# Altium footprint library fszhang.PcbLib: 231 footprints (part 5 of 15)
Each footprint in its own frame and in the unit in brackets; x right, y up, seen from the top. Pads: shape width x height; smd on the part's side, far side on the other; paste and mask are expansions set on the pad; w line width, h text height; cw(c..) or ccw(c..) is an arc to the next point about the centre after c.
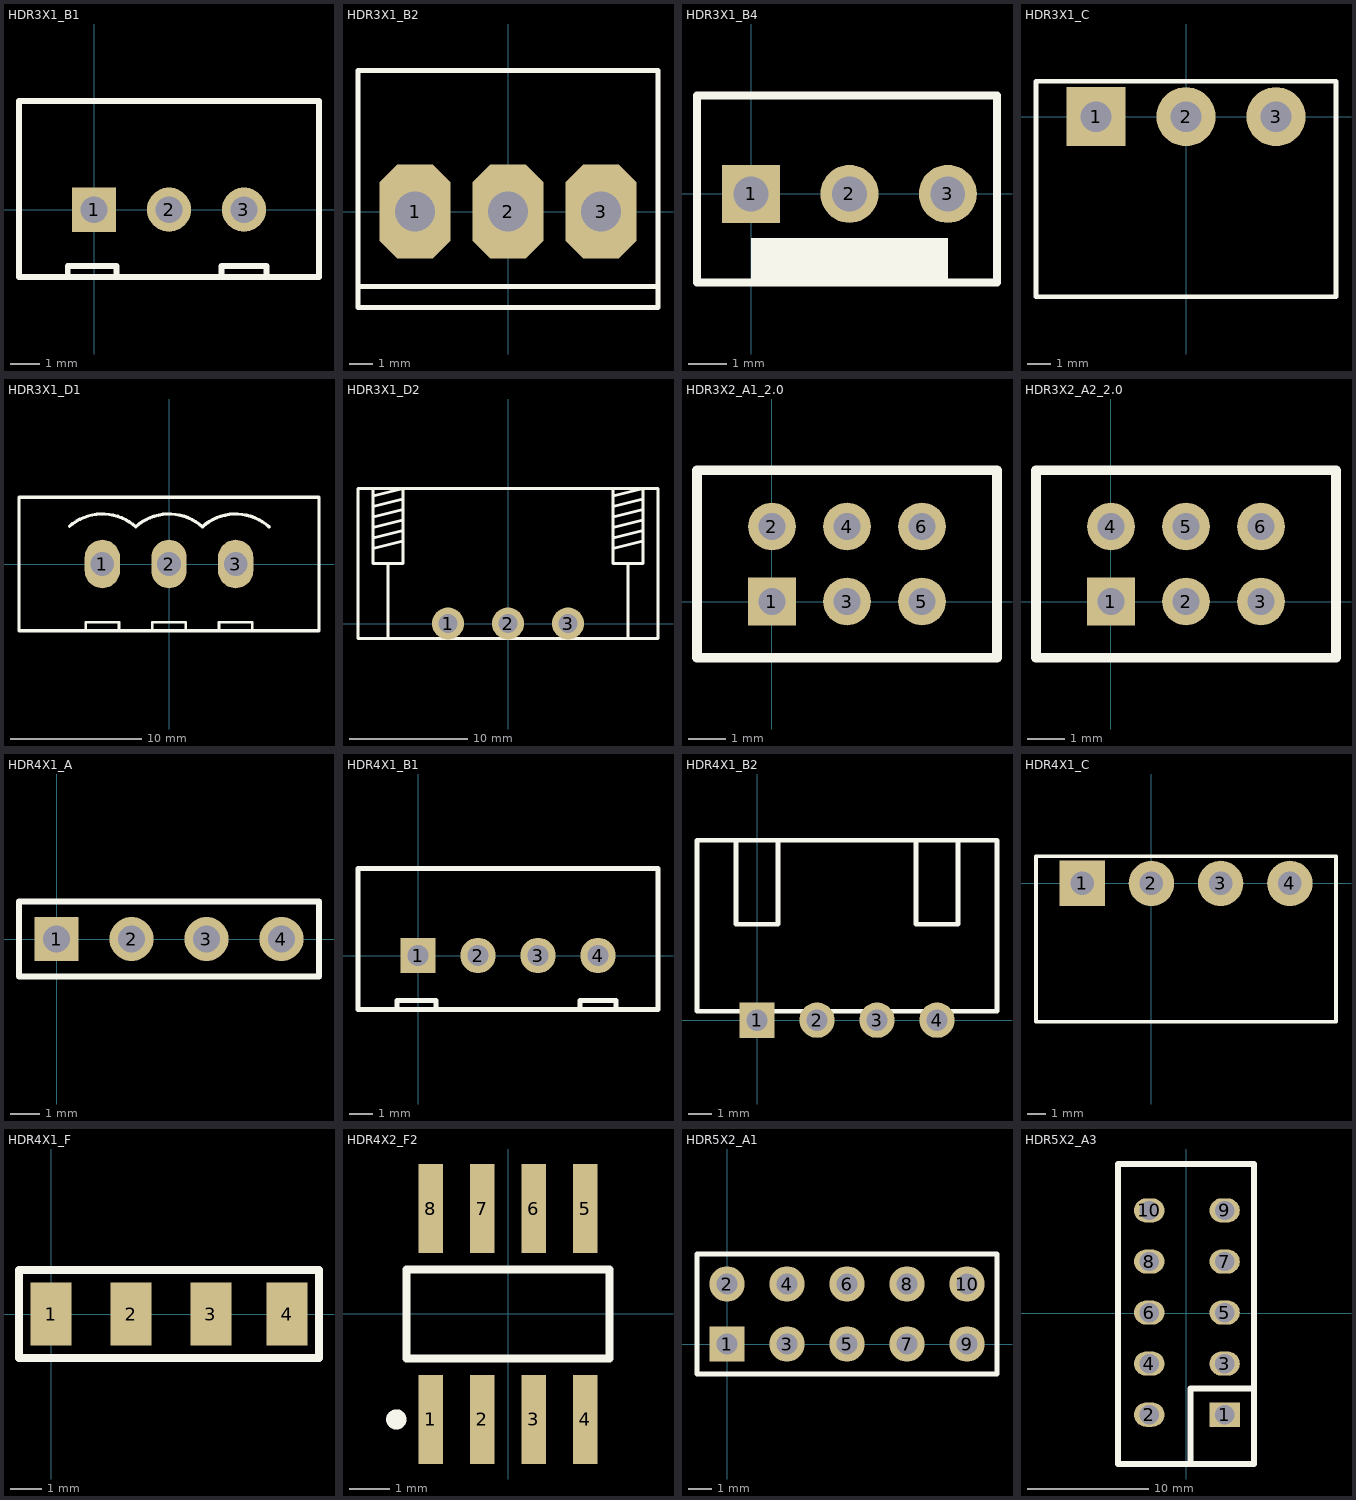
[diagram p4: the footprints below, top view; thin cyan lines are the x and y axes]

## HDR3X1_B1 [mm] "Connector; Header; 3 Position"
height 1.5
pads (3):
  rect 1.5x1.5 hole 0.9: 1(0,0)
  round 1.5 hole 0.9: 2(2.54,0) 3(5.08,0)
Top Overlay:
  lines w0.2: -0.889,-2.286 -0.889,-1.905 0.762,-1.905 0.762,-2.286 ; 4.318,-2.286 4.318,-1.905 5.842,-1.905 5.842,-2.286 ; -2.54,-2.286 -2.54,3.683 7.62,3.683 7.62,-2.286 -2.54,-2.286
3D body: height 1.5, standoff 0, extent -2.54,-2.286 7.62,3.683

## HDR3X1_B2 [mm] "Connector; Header; 3 Position"
height 1.5
pads (3):
  oct 3x4 hole 1.7: 1(-3.937,0) 2(0,0) 3(3.937,0)
Top Overlay:
  lines w0.2: -6.35,-3.175 6.35,-3.175 ; -2.54,-4.064 2.54,-4.064 ; -6.35,-4.064 -6.35,5.969 6.35,5.969 6.35,-4.064 -6.35,-4.064

## HDR3X1_B4 [mm] "Connector; Header; 4 Position"
height 1.6
pads (3):
  rect 1.5x1.5 hole 0.9: 1(0,0)
  round 1.5 hole 0.9: 2(2.54,0) 3(5.08,0)
Top Overlay:
  rectangle: 0,-2.286 5.08,-1.143
  lines w0.2: -1.397,-2.286 6.35,-2.286 6.35,2.54 -1.397,2.54 -1.397,-2.286
3D body: height 1.5, standoff 0, extent -1.397,-2.286 6.35,2.54

## HDR3X1_C [mm] "3.81MM接插件"
height 7
pads (3):
  rect 2.5x2.5 hole 1.3: 1(-3.81,0)
  round 2.5 hole 1.3: 2(0,0) 3(3.81,0)
Top Overlay:
  lines w0.2: -6.35,-7.62 -6.35,1.5 6.35,1.5 6.35,-7.62 -6.35,-7.62
3D body: height 6, standoff 0, extent -6.35,-7.62 6.35,1.397

## HDR3X1_D1 [mm] "5.08mm端子"
height 12.7
pads (3):
  oval 2.7x3.7 hole 1.8: 1(-5.08,0) 2(0,0) 3(5.08,0)
Top Overlay:
  lines w0.2: -6.35,-5.08 -6.35,-4.445 -3.81,-4.445 -3.81,-5.08 ; -1.27,-5.08 -1.27,-4.445 1.27,-4.445 1.27,-5.08 ; 3.81,-5.08 3.81,-4.445 6.35,-4.445 6.35,-5.08
  lines w0.254: -7.58,2.875 cw(c-5.08,0) -2.517,2.819 ; -2.538,2.842 cw(c0,0) 2.563,2.819 ; 2.542,2.842 cw(c5.08,0) 7.643,2.819 ; -11.43,-5.08 11.43,-5.08 11.43,5.08 -11.43,5.08 -11.43,-5.08

## HDR3X1_D2 [mm] "5.08mm端子"
height 12.7
pads (3):
  round 2.7 hole 1.6: 1(-5.08,0) 2(0,0) 3(5.08,0)
Top Overlay:
  lines w0.254: -11.43,6.35 -8.89,6.985 ; -11.43,7.239 -8.89,7.874 ; -11.43,8.128 -8.89,8.763 ; -11.43,9.017 -8.89,9.652 ; -11.43,9.906 -8.89,10.541 ; -11.43,10.795 -8.89,11.43 -8.89,5.08 -11.43,5.08 -11.43,11.43 ; -10.16,-1.27 -10.16,5.08 ; 8.89,6.35 11.43,6.985 ; 8.89,7.239 11.43,7.874 ; 8.89,8.128 11.43,8.763 ; 8.89,9.017 11.43,9.652 ; 8.89,9.906 11.43,10.541 ; 8.89,10.795 11.43,11.43 11.43,5.08 8.89,5.08 8.89,11.43 ; 10.16,-1.27 10.16,5.08 ; -12.7,-1.27 -12.7,11.43 12.7,11.43 12.7,-1.27 -12.7,-1.27

## HDR3X2_A1_2.0 [mm]
height 8
pads (6):
  rect 1.27x1.27 hole 0.711: 1(0,0)
  round 1.27 hole 0.711: 2(0,2) 3(2,0) 4(2,2) 5(4,0) 6(4,2)
Top Overlay:
  lines w0.254: -2,-1.5 6,-1.5 6,3.5 -2,3.5 -2,-1.5

## HDR3X2_A2_2.0 [mm]
height 8
pads (6):
  rect 1.27x1.27 hole 0.711: 1(0,0)
  round 1.27 hole 0.711: 2(2,0) 3(4,0) 4(0,2) 5(2,2) 6(4,2)
Top Overlay:
  lines w0.254: -2,-1.5 6,-1.5 6,3.5 -2,3.5 -2,-1.5

## HDR4X1_A [mm] "Connector; Header; 4 Position"
height 1.6
pads (4):
  rect 1.5x1.5 hole 0.9: 1(0,0)
  round 1.5 hole 0.9: 2(2.54,0) 3(5.08,0) 4(7.62,0)
Top Overlay:
  lines w0.2: -1.27,-1.27 -1.27,1.27 8.89,1.27 8.89,-1.27 -1.27,-1.27

## HDR4X1_B1 [mm] "Connector; Header; 4 Position"
height 1.6
pads (4):
  rect 1.5x1.5 hole 0.9: 1(0,0)
  round 1.5 hole 0.9: 2(2.54,0) 3(5.08,0) 4(7.62,0)
Top Overlay:
  lines w0.2: -0.889,-2.286 -0.889,-1.905 0.762,-1.905 0.762,-2.286 ; 6.858,-2.286 6.858,-1.905 8.382,-1.905 8.382,-2.286 ; -2.54,-2.286 -2.54,3.683 10.16,3.683 10.16,-2.286 -2.54,-2.286
3D body: height 1.5, standoff 0, extent -2.413,-2.159 10.033,3.556

## HDR4X1_B2 [mm] "Connector; Header; 4 Position"
height 1.6
pads (4):
  rect 1.5x1.5 hole 0.9: 1(0,0)
  round 1.5 hole 0.9: 2(2.54,0) 3(5.08,0) 4(7.62,0)
Top Overlay:
  lines w0.2: -0.889,7.62 -0.889,4.064 0.889,4.064 0.889,7.62 ; 6.731,7.62 6.731,4.064 8.509,4.064 8.509,7.62 ; -2.54,0.381 10.16,0.381 10.16,7.62 -2.54,7.62 -2.54,0.381
3D body: height 1.5, standoff 0, extent -2.54,0.381 10.16,7.62

## HDR4X1_C [mm] "3.81MM接插件"
height 7
pads (4):
  rect 2.5x2.5 hole 1.3: 1(-3.81,0)
  round 2.5 hole 1.3: 2(0,0) 3(3.81,0) 4(7.62,0)
Top Overlay:
  lines w0.2: -6.35,-7.62 -6.35,1.5 10.16,1.5 10.16,-7.62 -6.35,-7.62
3D body: height 6, standoff 0, extent -6.35,-7.62 10.16,1.5

## HDR4X1_F [mm]
pads (4):
  rect 1.3x2 smd: 1(0,0) 2(2.54,0) 3(5.08,0) 4(7.493,0)
Top Overlay:
  lines w0.254: -1.016,-1.397 8.509,-1.397 8.509,1.397 -1.016,1.397 -1.016,-1.397

## HDR4X2_F2 [mm]
height 1.75
pads (8):
  rect 0.6x2.2 smd: 1(-1.905,-2.6) 2(-0.635,-2.6) 3(0.635,-2.6) 4(1.905,-2.6) 5(1.905,2.6) 6(0.635,2.6) 7(-0.635,2.6) 8(-1.905,2.6)
Top Overlay:
  circle w0.25: c-2.755,-2.6 r0.125
  lines w0.2: -2.5,-1.1 -2.5,-0.367 -2.5,1.1 2.5,1.1 2.5,-1.1 -2.5,-1.1

## HDR5X2_A1 [mm] "Connector; Header; 5x2 Position"
height 1.2
pads (10):
  rect 1.5x1.5 hole 0.9: 1(0,0)
  round 1.5 hole 0.9: 2(0,2.54) 3(2.54,0) 4(2.54,2.54) 5(5.08,0) 6(5.08,2.54) 7(7.62,0) 8(7.62,2.54) 9(10.16,0) 10(10.16,2.54)
Top Overlay:
  lines w0.2: -1.27,-1.27 11.43,-1.27 11.43,3.81 -1.27,3.81 -1.27,-1.27

## HDR5X2_A3 [mm]
pads (10):
  rect 2.5x2 hole 1.6: 1(3.144,-8.351)
  oval 2.5x2 hole 1.6: 2(-3.056,-8.351) 3(3.144,-4.151) 4(-3.056,-4.151) 5(3.144,0.049) 6(-3.056,0.049) 7(3.144,4.249) 8(-3.056,4.249) 9(3.144,8.449) 10(-3.056,8.449)
Top Overlay:
  lines w0.5: 0.35,-12.415 0.35,-6.192 5.557,-6.192 ; -5.619,-12.415 -5.619,12.274 5.557,12.274 5.557,-12.415 -5.619,-12.415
